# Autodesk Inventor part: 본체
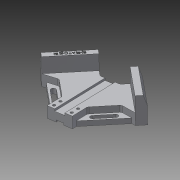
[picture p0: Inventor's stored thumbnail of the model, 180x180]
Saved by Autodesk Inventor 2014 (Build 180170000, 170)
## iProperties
Created: 2020-05
Part Number: 본체
Material: 알루미늄 6061
Document SubType Name: Modeling
Designer: kh
Density: 2.71 g/cm^3
Appearance: 알루미늄 - 평지
Mass: 573.739 g
Surface Area: 407.173 cm^2
Volume: 211.712 cm^3
Author: kh
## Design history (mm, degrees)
sketch "스케치6"
  geometry: L1 (0, 84.853)-(-84.853, 0); L2 (-84.853, 0)-(0, -84.853); L3 (0, -84.853)-(84.853, 0); L4 (84.853, 0)-(0, 84.853); 1 further point
  constraints: 8 end point, 3 horizontal alignment, 2 vertical alignment, 1 perpendicular
  dimensions: "d26" = 120 distance of L1.start L1.end; "d27" = 120 distance of L3.end L1.start; "d28" = 120 distance of L2.end L3.end
extrude "돌출4" new body sketch "스케치6" distance "d29" = 42; taper "d30" = 0 deg
sketch "스케치8"
  geometry: L1 (0, -84.853)-(84.853, 0) reference; L2 (-84.853, 0)-(0, -84.853) reference; L3 (-20, -64.853)-(20, -64.853); L4 (20, -64.853)-(0, -84.853); L5 (-20, -64.853)-(0, -84.853); 1 further point
  constraints: 6 end point, 2 collinear, 2 point on line, 1 horizontal
  dimensions: "d34" = 20 distance from line of L1.start L3
extrude "돌출5" cut sketch "스케치8" stored distance "d35" = 10; taper "d36" = 0 deg
sketch "스케치9"
  geometry: L1 (0, 84.853)-(-84.853, 0) reference; L2 (84.853, 0)-(0, 84.853) reference; L3 (-35.355, 49.497)-(-16.005, 30.147); L4 (-16.005, 30.147)-(16.005, 30.147); L5 (16.005, 30.147)-(35.355, 49.497); L6 (-20, -64.853)-(20, -64.853) reference; L7 (-35.355, 49.497)-(0, 84.853); L8 (0, 84.853)-(35.355, 49.497); 2 further points
  constraints: 10 end point, 2 collinear, 2 point on line, 1 horizontal, 1 midpoint, 1 parallel, 1 perpendicular, 1 vertical alignment
  dimensions: "d38" = 50 distance of L1.start L5.end; "d39" = 95 distance between parallel lines of L6 L4
extrude "돌출6" cut sketch "스케치9" stored distance "d40" = 10; taper "d41" = 0 deg
sketch "스케치10"
  geometry: L1 (-35.355, 49.497)-(-84.853, 0) reference; L2 (35.355, 49.497)-(16.005, 30.147) reference; L3 (16.005, 30.147)-(-16.005, 30.147) reference; L4 (-16.005, 30.147)-(-35.355, 49.497) reference; L5 (-35.355, 49.497)-(-84.853, 0) reference; L6 (-84.853, 0)-(-20, -64.853) reference; L7 (-20, -64.853)-(20, -64.853) reference; L8 (20, -64.853)-(84.853, 0) reference; L9 (84.853, 0)-(35.355, 49.497) reference; L10 (-74.246, -10.607)-(-24.749, 38.891); L11 (24.749, 38.891)-(74.246, -10.607); L12 (-24.749, 38.891)-(-16.005, 30.147); L13 (16.005, 30.147)-(24.749, 38.891); L14 (-16.005, 30.147)-(16.005, 30.147); L15 (-74.246, -10.607)-(-20, -64.853); L16 (-20, -64.853)-(20, -64.853); L17 (20, -64.853)-(74.246, -10.607); 1 further point
  constraints: 16 end point, 4 collinear, 4 point on line, 3 perpendicular, 1 parallel
  dimensions: "d42" = 15 distance between parallel lines of L1 L10; "d43" = 15 distance between parallel lines of L9 L11
extrude "돌출7" cut sketch "스케치10" distance "d44" = 24; taper "d45" = 0 deg
sketch "스케치11"
  geometry: L1 (16.005, 30.147)-(24.749, 38.891) reference; L2 (-16.005, 30.147)-(16.005, 30.147) reference; L3 (-24.749, 38.891)-(-16.005, 30.147) reference; L4 (-74.246, -10.607)-(-24.749, 38.891) reference; L5 (-20, -64.853)-(-74.246, -10.607) reference; L6 (20, -64.853)-(-20, -64.853) reference; L7 (74.246, -10.607)-(20, -64.853) reference; L8 (24.749, 38.891)-(74.246, -10.607) reference; L9 (-74.246, -10.607)-(-49.497, -7.071); L10 (-49.497, -7.071)-(-20, -36.569); L11 (-20, -36.569)-(-20, -64.853); L12 (20, -64.853)-(20, -36.569); L13 (-74.246, -10.607)-(-20, -64.853); L14 (20, -64.853)-(74.246, -10.607); L15 (-35.355, 49.497)-(-84.853, 0) reference; L16 (20, -36.569)-(49.497, -7.071); L17 (49.497, -7.071)-(74.246, -10.607); L18 (84.853, 0)-(35.355, 49.497) reference; L19 (-68.059, -9.723)-(-20, -57.782); L20 (20, -57.782)-(68.059, -9.723); 1 further point
  constraints: 20 end point, 5 parallel, 4 point on line, 1 perpendicular, 1 vertical
  dimensions: "d48" = 30 distance from line of L9.end L15; "d49" = 20 distance between parallel lines of L5 L10; "d51" = 20 distance between parallel lines of L7 L16; "d52" = 30 distance from line of L18 L16.end; "d55" = 5 distance between parallel lines of L19 L5; "d56" = 5 distance between parallel lines of L7 L20
  node "투영된 루프2"
extrude "돌출8" cut sketch "스케치11" distance "d53" = 10; taper "d54" = 0 deg
extrude "돌출9" cut sketch "스케치11" stored distance "d57" = 10; taper "d58" = 0 deg
sketch "스케치13"
  geometry: L1 (-68.059, -9.723)-(-20, -57.782) reference; L2 (-20, -36.569)-(-20, -57.782) reference; L3 (-49.497, -7.071)-(-20, -36.569) reference; L4 (-68.059, -9.723)-(-49.497, -7.071) reference; L5 (20, -57.782)-(68.059, -9.723) reference; L6 (49.497, -7.071)-(68.059, -9.723) reference; L7 (20, -36.569)-(49.497, -7.071) reference; L8 (20, -57.782)-(20, -36.569) reference; L9 (-49.497, -18.385)-(-29.698, -38.184); L10 (-52.326, -21.213)-(-32.527, -41.012); L11 (-26.87, -35.355)-(-46.669, -15.556); L12 (-35.355, 49.497)-(-84.853, 0) reference; L13 (-84.853, 0)-(-74.246, -10.607) reference; L14 (0, 0)-(0, -13.54); L15 (26.87, -35.355)-(46.669, -15.556); L16 (52.326, -21.213)-(32.527, -41.012); A1 r 4 centre (-49.497, -18.385) between (-46.669, -15.556) and (-52.326, -21.213); A2 r 4 centre (-29.698, -38.184) between (-32.527, -41.012) and (-26.87, -35.355); A3 r 4 centre (49.497, -18.385) between (52.326, -21.213) and (46.669, -15.556); A4 r 4 centre (29.698, -38.184) between (26.87, -35.355) and (32.527, -41.012); 1 further point
  constraints: 14 end point, 8 point on circle, 6 symmetric about line, 4 centre point, 4 tangent, 3 parallel, 1 midpoint, 2 other
  dimensions: "d59" = 38 distance from line of L12 L9.start; "d60" = 28 distance of L9.end L9.start; "d61" = 8 distance between parallel lines of L11 L10; "d63" = 12 distance from line of L13 point (-39.598, -28.284)
extrude "돌출10" cut sketch "스케치13" stored distance "d64" = 10; taper "d65" = 0 deg
sketch "스케치14"
  geometry: L1 (40, 0)-(0, 0) reference; L2 (12, 0)-(12, -3.5); L3 (12, -3.5)-(28, -3.5); L4 (28, -3.5)-(28, 0); L5 (40, -18)-(0, -18) reference; L6 (14, -15)-(26, -15); L7 (26, -15)-(26, -18); L8 (26, -18)-(14, -18); L9 (14, -18)-(14, -15); L10 (12, 0)-(28, 0); 5 further points
  constraints: 16 end point, 5 perpendicular, 4 midpoint, 3 point on line, 2 parallel, 1 coincident, 1 horizontal, 1 vertical alignment
  dimensions: "d66" = 16 distance of L2.end L3.end; "d67" = 3.5 distance of L3.end L4.end; "d68" = 12 distance of L6.start L6.end; "d69" = 3 distance of L6.end L7.end
extrude "돌출11" cut sketch "스케치14" stored distance "d70" = 10; taper "d71" = 0 deg
sketch "스케치16"
  geometry: L1 (-6, -30.147)-(-6, 64.853) reference; L2 (-6, 64.853)-(-20, 64.853) reference; L3 (-20, 64.853)-(-20, 57.782) reference; L4 (-20, 57.782)-(-68.059, 9.723) reference; L5 (-68.059, 9.723)-(-74.246, 10.607) reference; L6 (-84.853, 0)-(-74.246, 10.607) reference; L7 (-35.355, -49.497)-(-84.853, 0) reference; L8 (-35.355, -49.497)-(-16.005, -30.147) reference; L9 (-16.005, -30.147)-(-6, -30.147) reference; L10 (-26.87, 35.355)-(-46.669, 15.556) reference; L11 (-52.326, 21.213)-(-32.527, 41.012) reference; L12 (20, 57.782)-(20, 36.569) reference; L13 (6, 64.853)-(6, -30.147) reference; L14 (6, -30.147)-(16.005, -30.147) reference; L15 (16.005, -30.147)-(35.355, -49.497) reference; L16 (84.853, 0)-(35.355, -49.497) reference; L17 (74.246, 10.607)-(84.853, 0) reference; L18 (74.246, 10.607)-(68.059, 9.723) reference; L19 (68.059, 9.723)-(20, 57.782) reference; L20 (20, 57.782)-(20, 64.853) reference; L21 (20, 64.853)-(6, 64.853) reference; L22 (32.527, 41.012)-(52.326, 21.213) reference; L23 (46.669, 15.556)-(26.87, 35.355) reference; A1 r 4 centre (-29.698, 38.184) between (-26.87, 35.355) and (-32.527, 41.012) reference; A2 r 4 centre (-49.497, 18.385) between (-52.326, 21.213) and (-46.669, 15.556) reference; A3 r 4 centre (29.698, 38.184) between (32.527, 41.012) and (26.87, 35.355) reference; A4 r 4 centre (49.497, 18.385) between (46.669, 15.556) and (52.326, 21.213) reference; 5 further points
  constraints: 2 horizontal alignment, 2 vertical alignment
  dimensions: "d77" = 6 distance from line of L21 point (14, 58.853); "d78" = 12 distance of point (14, 58.853) point (14, 46.853); "d79" = 14 horizontal distance of point (0, 0) point (14, 58.853); "d80" = 28 distance of point (14, 58.853) point (-14, 58.853)
hole "구멍1" sketch "스케치16" at (-14, 58.853), (-14, 46.853), (14, 58.853), (14, 46.853) diameter "d81" = 4.5; stored, may be unused: countersink angle "d85" = 90 deg, drill point angle "d87" = 118 deg; dims "d82" = 6, "d83" = 8, "d84" = 10, "d86" = 8
chamfer "모따기1" distance "d88" = 5; stored, may be unused: second distance "d89" = 15, angle "d90" = 45 deg
chamfer "모따기2" distance "d91" = 5; stored, may be unused: second distance "d92" = 15, angle "d93" = 45 deg
fillet "모깎기1" dims "d94" = 5
sketch "스케치17"
  geometry: L1 (-81.317, -3.536)-(-31.82, 45.962) reference; L2 (-81.317, -3.536)-(-74.246, -10.607) reference; L3 (-74.246, -10.607)-(-24.749, 38.891) reference; L4 (-24.749, 38.891)-(-31.82, 45.962) reference; L5 (-37.614, 27.933)-(-63.288, 2.259); L6 (-63.288, 2.259)-(-68.452, 7.422); L7 (-68.452, 7.422)-(-42.778, 33.096); L8 (-42.778, 33.096)-(-37.614, 27.933); L9 (-63.288, 2.259)-(-42.778, 33.096); L10 (-68.452, 7.422)-(-37.614, 27.933); 4 further points
  constraints: 4 end point, 2 coincident, 1 midpoint, 2 other
  dimensions: "d95" = 5 distance from line of L3 point (-53.033, 17.678); "d96" = 35 distance from line of L4 point (-53.033, 17.678)
feature "엠보싱1" sketch "스케치17" dims "d26" = 120, "d38" = 50, "d39" = 95, "d97" = 0.5, "d98" = 0
fillet "모깎기2" dims "d99" = 5
node "솔리드2"
node "투영된 루프1"
node "투영된 루프3"
node "투영된 루프4"
node "투영된 루프7"
node "투영된 루프8"
node "투영된 루프9"
